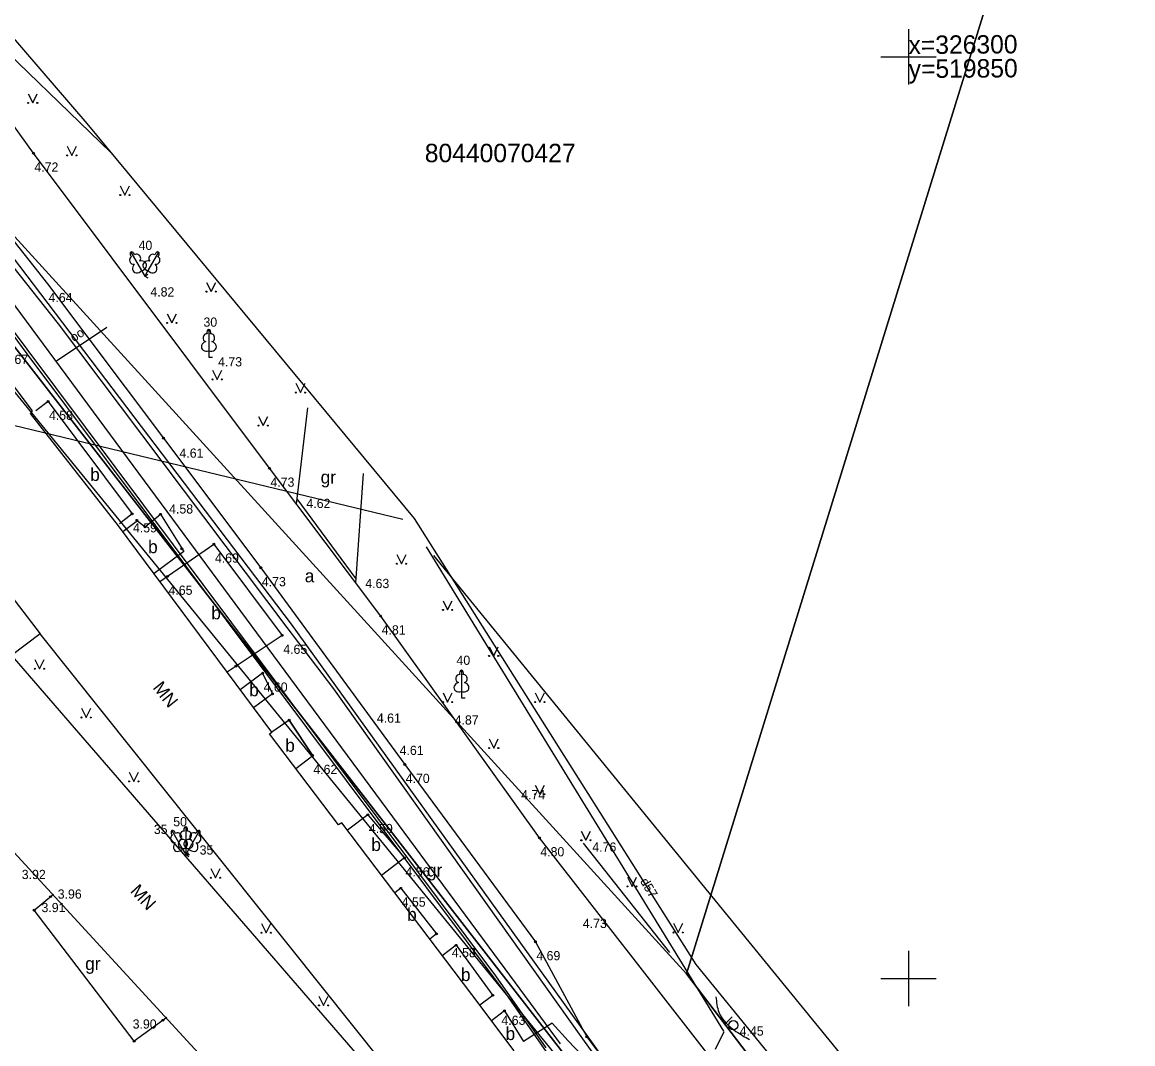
# Model space of a CAD drawing. Extents: x 519536 to 519949, y 326041 to 326519.
# Drawn here: x 519801.9 to 519862.2, y 326246.5 to 326301.9 of the extents above; entities that cross this region are included whole.
import ezdxf

# ---------------------------------------------------------------- set-up
doc = ezdxf.new("R2010")
doc.units = 0
for name, color, linetype in [('APGR_SARK_####_####_#', 7, 'Continuous'), ('BUVE_EKAS_####_####_#', 7, 'Continuous'), ('BUVE_EKAS_BPAL_####_#', 7, 'Continuous'), ('BUVE_EKAS_RAKS_TKST_#', 7, 'Continuous'), ('BUVE_ELEM_####_####_#', 7, 'Continuous'), ('CELI_CMAL_####_####_#', 7, 'Continuous'), ('CELI_CSEG_####_TKST_#', 7, 'Continuous'), ('CELI_TAKA_####_####_#', 7, 'Continuous'), ('ELEK_VADP_ZSPR_####_#', 7, 'Continuous'), ('GAZE_VADP_ASP1_####_#', 7, 'Continuous'), ('GAZE_VADP_ASP1_TKST_#', 7, 'Continuous'), ('GEOD_ELEM_####_####_#', 7, 'Continuous'), ('GEOD_KORD_####_TKST_#', 7, 'Continuous'), ('RAMI_UZMR_####_####_#', 7, 'Continuous'), ('RELJ_AATZ_####_TKST_#', 7, 'Continuous'), ('RELJ_ELEM_####_####_#', 7, 'Continuous'), ('RELJ_HORZ_PAMT_####_#', 7, 'Continuous'), ('ROBZ_IERR_####_####_#', 7, 'Continuous'), ('ROBZ_PROJ_####_####_#', 7, 'Continuous'), ('ROBZ_UZMR_####_####_#', 7, 'Continuous'), ('ROBZ_UZMR_####_TKST_#', 7, 'Continuous'), ('SAKK_IZVK_####_TKST_#', 7, 'Continuous'), ('SAKK_KKAN_####_####_#', 7, 'Continuous'), ('SAKT_VADV_PKAB_####_#', 7, 'Continuous'), ('TERT_DIAM_####_TKST_#', 7, 'Continuous'), ('TERT_ELEM_####_####_#', 7, 'Continuous'), ('TERT_KRND_####_####_#', 7, 'Continuous')]:
    doc.layers.add(name, color=color, linetype=linetype)

msp = doc.modelspace()

# ---------------------------------------------------------------- linework, layer by layer
at = {"layer": 'APGR_SARK_####_####_#'}
for p, q in [((519771.502, 326318.577), (519839.505, 326235.263)), ((519824.229, 326272.956), (519848.672, 326243.009))]:
    msp.add_line(p, q, dxfattribs=at)
at = {"layer": 'BUVE_EKAS_####_####_#'}
for points in [[(519826.305, 326249.13), (519819.255, 326258.455), (519819.074, 326258.332), (519815.338, 326263.273), (519815.461, 326263.364), (519807.157, 326274.561), (519802.379, 326280.656), (519802.486, 326280.797), (519797.912, 326286.858)], [(519801.084, 326271.092), (519802.904, 326268.709)], [(519815.97, 326241.067), (519794.322, 326264.64), (519799.853, 326269.244)], [(519799.853, 326269.244), (519820.912, 326244.923)], [(519821.513, 326245.392), (519802.904, 326268.709)], [(519828.616, 326246.073), (519826.305, 326249.13)]]:
    msp.add_lwpolyline(points, dxfattribs=at)
at = {"layer": 'BUVE_EKAS_BPAL_####_#'}
msp.add_lwpolyline([(519802.904, 326268.709), (519801.347, 326267.519)], dxfattribs=at)
at = {"layer": 'BUVE_ELEM_####_####_#'}
msp.add_circle((519840.493, 326247.47), 0.25, dxfattribs=at)
at = {"layer": 'CELI_CMAL_####_####_#'}
for p, q in [((519803.331, 326281.307), (519802.665, 326280.804)), ((519816.809, 326275.728), (519817.415, 326280.965)), ((519820.019, 326271.461), (519820.445, 326277.403)), ((519807.885, 326275.204), (519807.208, 326274.673)), ((519808.189, 326274.831), (519807.394, 326274.241)), ((519810.687, 326273.16), (519809.08, 326271.968)), ((519814.97, 326266.565), (519813.755, 326265.664)), ((519815.496, 326265.441), (519814.48, 326264.687)), ((519817.687, 326262.08), (519816.766, 326261.384)), ((519820.679, 326258.89), (519819.564, 326258.047)), ((519822.667, 326256.542), (519821.416, 326255.596)), ((519802.583, 326253.712), (519803.625, 326254.58)), ((519822.457, 326254.899), (519822.13, 326254.652)), ((519808, 326246.596), (519802.583, 326253.712)), ((519824.402, 326252.422), (519824.029, 326252.14)), ((519825.464, 326251.806), (519824.712, 326251.237)), ((519827.448, 326249.09), (519826.74, 326248.555)), ((519828.079, 326248.249), (519827.374, 326247.716)), ((519809.77, 326247.892), (519808, 326246.596)), ((519830.678, 326247.588), (519829.123, 326246.591)), ((519830.678, 326247.588), (519831.546, 326246.618)), ((519831.546, 326246.618), (519832.626, 326245.477))]:
    msp.add_line(p, q, dxfattribs=at)
for points in [[(519839.189, 326245.804), (519829.977, 326257.629), (519821.37, 326269.665), (519815.34, 326277.68), (519802.539, 326294.771), (519798.724, 326300.05), (519793.164, 326307.804), (519787.022, 326315.974)], [(519797.68, 326294.786), (519803.307, 326287.694), (519809.593, 326279.318), (519814.875, 326272.28), (519822.676, 326261.61), (519829.759, 326251.994), (519832.548, 326246.837), (519835.264, 326243.212)], [(519803.331, 326281.307), (519807.885, 326275.204)], [(519808.189, 326274.831), (519808.589, 326274.501), (519809.428, 326275.187), (519810.687, 326273.16)], [(519809.402, 326271.535), (519812.33, 326273.562), (519816.035, 326268.616), (519813.039, 326266.63)], [(519814.97, 326266.565), (519815.496, 326265.441)], [(519817.687, 326262.08), (519816.406, 326264.014), (519815.461, 326263.364)], [(519816.406, 326264.014), (519817.687, 326262.08)], [(519820.679, 326258.89), (519822.667, 326256.542)], [(519822.457, 326254.899), (519824.402, 326252.422)], [(519825.464, 326251.806), (519827.448, 326249.09)], [(519828.079, 326248.249), (519829.123, 326246.591)]]:
    msp.add_lwpolyline(points, dxfattribs=at)
at = {"layer": 'CELI_TAKA_####_####_#'}
msp.add_lwpolyline([(519820.035, 326271.683), (519816.843, 326276.026)], dxfattribs=at)
at = {"layer": 'ELEK_VADP_ZSPR_####_#'}
msp.add_line((519827.61, 326250.148), (519799.349, 326287.942), dxfattribs=at)
for points in [[(519830.369, 326246.03), (519828.17, 326249.181), (519802.207, 326283.896), (519795.993, 326292.283), (519770.741, 326312.416), (519767.549, 326319.699), (519768.203, 326324.348), (519772.317, 326338.857)], [(519832.235, 326246.864), (519818.826, 326265.725), (519816.295, 326269.053), (519803.894, 326285.515), (519801.087, 326289.082)], [(519832.53, 326246.969), (519816.537, 326269.231), (519801.397, 326289.168)], [(519830.345, 326246.245), (519827.61, 326250.148)], [(519836.543, 326237.909), (519834.17, 326244.171), (519832.235, 326246.864)], [(519836.785, 326238.116), (519834.436, 326244.315), (519832.53, 326246.969)]]:
    msp.add_lwpolyline(points, dxfattribs=at)
at = {"layer": 'GAZE_VADP_ASP1_####_#'}
for points in [[(519799.445, 326301.842), (519806.723, 326294.826)], [(519823.837, 326273.416), (519839.954, 326247.14)], [(519839.519, 326246.171), (519840, 326247.131)]]:
    msp.add_lwpolyline(points, dxfattribs=at)
at = {"layer": 'GEOD_ELEM_####_####_#'}
for p, q in [((519850, 326301.5), (519850, 326300)), ((519848.5, 326300), (519850, 326300)), ((519850, 326300), (519850, 326298.5)), ((519850, 326300), (519851.5, 326300)), ((519850, 326251.5), (519850, 326250)), ((519848.5, 326250), (519850, 326250)), ((519850, 326250), (519850, 326248.5)), ((519850, 326250), (519851.5, 326250))]:
    msp.add_line(p, q, dxfattribs=at)
at = {"layer": 'RAMI_UZMR_####_####_#'}
msp.add_lwpolyline([(519677.714, 326342.785), (519698.5, 326350), (519731.501, 326357.892), (519737.588, 326345.92), (519745.762, 326337.624), (519750.101, 326341.721), (519757.06, 326345.369), (519768.285, 326348.755), (519787.076, 326359.753), (519805.421, 326337.748), (519789.141, 326322.825), (519795, 326316.434), (519793.447, 326310.334), (519805.429, 326296.386), (519823.19, 326274.962), (519838.453, 326250.764), (519857.773, 326227.07), (519873.021, 326209.453), (519881.37, 326184.273)], dxfattribs=at)
at = {"layer": 'RELJ_ELEM_####_####_#'}
for centre in [(519802.539, 326294.771), (519803.331, 326281.307), (519809.593, 326279.318), (519815.34, 326277.68), (519807.885, 326275.204), (519809.428, 326275.187), (519808.154, 326274.86), (519808.589, 326274.501), (519810.59, 326273.317), (519812.33, 326273.562), (519814.875, 326272.28), (519809.813, 326271.819), (519821.37, 326269.665), (519816.035, 326268.616), (519813.52, 326266.949), (519814.97, 326266.565), (519815.496, 326265.441), (519816.406, 326264.014), (519817.668, 326262.1), (519822.676, 326261.61), (519820.679, 326258.89), (519829.977, 326257.629), (519822.667, 326256.542), (519822.457, 326254.899), (519803.462, 326254.444), (519802.583, 326253.712), (519824.402, 326252.422), (519825.464, 326251.806), (519829.759, 326251.994), (519827.448, 326249.09), (519828.079, 326248.249), (519809.56, 326247.738), (519832.548, 326246.837), (519808, 326246.596)]:
    msp.add_circle(centre, 0.05, dxfattribs=at)
at = {"layer": 'RELJ_HORZ_PAMT_####_#'}
msp.add_line((519840.074, 326247.561), (519840.427, 326247.916), dxfattribs=at)
msp.add_spline([(519839.55, 326249.01), (519839.715, 326248.172), (519840.639, 326247.136), (519841.38, 326246.69)], degree=3, dxfattribs=at)
at = {"layer": 'ROBZ_IERR_####_####_#'}
for p, q in [((519837.956, 326250.254), (519857.532, 326313.584)), ((519866.128, 326213.288), (519837.956, 326250.254))]:
    msp.add_line(p, q, dxfattribs=at)
at = {"layer": 'ROBZ_PROJ_####_####_#'}
for p, q in [((519795.524, 326296.822), (519837.956, 326250.254)), ((519841.088, 326233.318), (519793.426, 326294.677)), ((519837.956, 326250.254), (519866.128, 326213.288))]:
    msp.add_line(p, q, dxfattribs=at)
at = {"layer": 'ROBZ_UZMR_####_####_#'}
for p, q in [((519857.532, 326313.584), (519837.956, 326250.254)), ((519837.956, 326250.254), (519795.524, 326296.822)), ((519793.426, 326294.677), (519841.088, 326233.318))]:
    msp.add_line(p, q, dxfattribs=at)
at = {"layer": 'SAKK_IZVK_####_TKST_#'}
msp.add_line((519803.731, 326283.481), (519806.512, 326285.339), dxfattribs=at)
at = {"layer": 'SAKK_KKAN_####_####_#'}
msp.add_line((519800.046, 326288.464), (519828.098, 326250.529), dxfattribs=at)
msp.add_lwpolyline([(519828.098, 326250.529), (519831.106, 326246.462)], dxfattribs=at)
at = {"layer": 'SAKT_VADV_PKAB_####_#'}
msp.add_lwpolyline([(519822.572, 326274.904), (519730.824, 326297.06)], dxfattribs=at)
at = {"layer": 'TERT_ELEM_####_####_#'}
for p, q in [((519802.25, 326298), (519802.5, 326297.5)), ((519802.5, 326297.5), (519802.75, 326298)), ((519804.371, 326295.154), (519804.621, 326294.654)), ((519804.621, 326294.654), (519804.871, 326295.154)), ((519807.25, 326293), (519807.5, 326292.5)), ((519807.5, 326292.5), (519807.75, 326293)), ((519808.401, 326288.411), (519808.574, 326288.11)), ((519808.747, 326288.411), (519808.574, 326288.11)), ((519808.574, 326288.11), (519808.747, 326288.21)), ((519808.574, 326288.11), (519808.747, 326288.01)), ((519811.923, 326287.764), (519812.173, 326287.264)), ((519812.173, 326287.264), (519812.423, 326287.764)), ((519809.797, 326286.068), (519810.047, 326285.568)), ((519810.047, 326285.568), (519810.297, 326286.068)), ((519812.052, 326284.056), (519812.052, 326283.709)), ((519812.052, 326283.709), (519812.252, 326283.709)), ((519812.25, 326283), (519812.5, 326282.5)), ((519812.5, 326282.5), (519812.75, 326283)), ((519816.769, 326282.291), (519817.019, 326281.791)), ((519817.019, 326281.791), (519817.269, 326282.291)), ((519814.75, 326280.5), (519815, 326280)), ((519815, 326280), (519815.25, 326280.5)), ((519822.25, 326273), (519822.5, 326272.5)), ((519822.5, 326272.5), (519822.75, 326273)), ((519824.75, 326270.5), (519825, 326270)), ((519825, 326270), (519825.25, 326270.5)), ((519827.25, 326268), (519827.5, 326267.5)), ((519827.5, 326267.5), (519827.75, 326268)), ((519802.614, 326267.309), (519802.864, 326266.809)), ((519802.864, 326266.809), (519803.114, 326267.309)), ((519824.75, 326265.5), (519825, 326265)), ((519825, 326265), (519825.25, 326265.5)), ((519825.749, 326265.569), (519825.749, 326265.222)), ((519829.75, 326265.5), (519830, 326265)), ((519830, 326265), (519830.25, 326265.5)), ((519825.749, 326265.222), (519825.949, 326265.222)), ((519805.149, 326264.663), (519805.399, 326264.163)), ((519805.399, 326264.163), (519805.649, 326264.663)), ((519827.25, 326263), (519827.5, 326262.5)), ((519827.5, 326262.5), (519827.75, 326263)), ((519807.728, 326261.199), (519807.978, 326260.699)), ((519807.978, 326260.699), (519808.228, 326261.199)), ((519829.75, 326260.5), (519830, 326260)), ((519830, 326260), (519830.25, 326260.5)), ((519832.25, 326258), (519832.5, 326257.5)), ((519832.5, 326257.5), (519832.75, 326258)), ((519810.623, 326257.028), (519810.796, 326256.727)), ((519810.796, 326257.074), (519810.796, 326256.727)), ((519810.969, 326257.028), (519810.796, 326256.727)), ((519810.796, 326256.727), (519810.969, 326256.827)), ((519810.796, 326256.727), (519810.996, 326256.727)), ((519810.796, 326256.727), (519810.969, 326256.627)), ((519812.16, 326255.972), (519812.41, 326255.472)), ((519812.41, 326255.472), (519812.66, 326255.972)), ((519834.75, 326255.5), (519835, 326255)), ((519835, 326255), (519835.25, 326255.5)), ((519814.915, 326252.984), (519815.165, 326252.484)), ((519815.165, 326252.484), (519815.415, 326252.984)), ((519837.25, 326253), (519837.5, 326252.5)), ((519837.5, 326252.5), (519837.75, 326253)), ((519818.025, 326249.044), (519818.275, 326248.544)), ((519818.275, 326248.544), (519818.525, 326249.044))]:
    msp.add_line(p, q, dxfattribs=at)
for points in [[(519807.824, 326289.409), (519808.401, 326288.411)], [(519808.018, 326289.253), (519808.016, 326289.253)], [(519809.324, 326289.409), (519808.747, 326288.411)], [(519809.285, 326289.163), (519809.285, 326289.164)], [(519812.052, 326285.209), (519812.052, 326284.056)], [(519812.142, 326284.977), (519812.141, 326284.978)], [(519825.749, 326266.722), (519825.749, 326265.569)], [(519825.839, 326266.49), (519825.838, 326266.491)], [(519810.796, 326258.227), (519810.796, 326257.074)], [(519810.046, 326258.026), (519810.623, 326257.028)], [(519810.24, 326257.87), (519810.238, 326257.87)], [(519810.886, 326257.995), (519810.885, 326257.996)], [(519811.546, 326258.026), (519810.969, 326257.028)], [(519811.507, 326257.78), (519811.507, 326257.781)]]:
    msp.add_lwpolyline(points, dxfattribs=at)
for centre, radius in [((519802.25, 326297.5), 0.028), ((519802.75, 326297.5), 0.0263), ((519804.37, 326294.653), 0.028), ((519804.87, 326294.653), 0.0263), ((519807.25, 326292.5), 0.028), ((519807.75, 326292.5), 0.0263), ((519811.922, 326287.264), 0.028), ((519812.422, 326287.264), 0.0263), ((519809.796, 326285.567), 0.028), ((519810.296, 326285.567), 0.0263), ((519812.25, 326282.5), 0.028), ((519812.75, 326282.5), 0.0263), ((519816.768, 326281.791), 0.028), ((519817.268, 326281.791), 0.0263), ((519814.75, 326280), 0.028), ((519815.25, 326280), 0.0263), ((519822.25, 326272.5), 0.028), ((519822.75, 326272.5), 0.0263), ((519824.75, 326270), 0.028), ((519825.25, 326270), 0.0263), ((519827.25, 326267.5), 0.028), ((519827.75, 326267.5), 0.0263), ((519802.613, 326266.808), 0.028), ((519803.113, 326266.808), 0.0263), ((519824.75, 326265), 0.028), ((519825.25, 326265), 0.0263), ((519829.75, 326265), 0.028), ((519830.25, 326265), 0.0263), ((519805.149, 326264.163), 0.028), ((519805.649, 326264.163), 0.0263), ((519827.25, 326262.5), 0.028), ((519827.75, 326262.5), 0.0263), ((519807.728, 326260.698), 0.028), ((519808.228, 326260.698), 0.0263), ((519829.75, 326260), 0.028), ((519830.25, 326260), 0.0263), ((519832.25, 326257.5), 0.028), ((519832.75, 326257.5), 0.0263), ((519812.16, 326255.472), 0.028), ((519812.66, 326255.472), 0.0263), ((519834.75, 326255), 0.028), ((519835.25, 326255), 0.0263), ((519814.914, 326252.483), 0.028), ((519815.414, 326252.483), 0.0263), ((519837.25, 326252.5), 0.028), ((519837.75, 326252.5), 0.0263), ((519818.025, 326248.544), 0.028), ((519818.525, 326248.544), 0.0263)]:
    msp.add_circle(centre, radius, dxfattribs=at)
for centre, major_axis, ratio, start_param, end_param in [((519807.935, 326288.96), (0.073, -0.203), 0.861323, 3.141593, 6.283185), ((519807.899, 326289.279), (0.075, -0.13), 0.707107, 3.14537, 5.287485), ((519807.899, 326289.279), (0.075, -0.13), 0.707107, 0.995701, 3.137816), ((519808.158, 326289.088), (0.14, -0.165), 0.861323, 0, 3.141593), ((519808.355, 326288.668), (-0.313, -0.071), 0.814445, 1.531171, 4.712389), ((519808.793, 326288.668), (0.313, -0.071), 0.814445, 1.570796, 4.752015), ((519808.99, 326289.088), (-0.14, -0.165), 0.861323, 3.141593, 6.283185), ((519809.249, 326289.279), (-0.075, -0.13), 0.707107, 3.14537, 5.287485), ((519809.213, 326288.96), (-0.073, -0.203), 0.861323, 0, 3.141593), ((519809.249, 326289.279), (-0.075, -0.13), 0.707107, 0.995701, 3.137816), ((519808.2, 326288.579), (0.218, 0.236), 0.814445, 1.570796, 4.752015), ((519808.948, 326288.579), (-0.218, 0.236), 0.814445, 1.531171, 4.712389), ((519811.924, 326284.764), (-0.039, -0.212), 0.861323, 3.141593, 6.283185), ((519812.052, 326285.059), (0, -0.15), 0.707107, 3.14537, 5.287485), ((519812.052, 326285.059), (0, -0.15), 0.707107, 0.995701, 3.137816), ((519812.18, 326284.764), (0.039, -0.212), 0.861323, 0, 3.141593), ((519811.962, 326284.302), (0.307, 0.095), 0.814445, 1.570796, 4.752015), ((519812.142, 326284.302), (-0.307, 0.095), 0.814445, 1.531171, 4.712389), ((519825.749, 326266.572), (0, -0.15), 0.707107, 3.14537, 5.287485), ((519825.749, 326266.572), (0, -0.15), 0.707107, 0.995701, 3.137816), ((519825.659, 326265.815), (0.307, 0.095), 0.814445, 1.570796, 4.752015), ((519825.621, 326266.277), (-0.039, -0.212), 0.861323, 3.141593, 6.283185), ((519825.839, 326265.815), (-0.307, 0.095), 0.814445, 1.531171, 4.712389), ((519825.877, 326266.277), (0.039, -0.212), 0.861323, 0, 3.141593), ((519810.796, 326258.077), (0, -0.15), 0.707107, 3.14537, 5.287485), ((519810.796, 326258.077), (0, -0.15), 0.707107, 0.995701, 3.137816), ((519810.157, 326257.577), (0.073, -0.203), 0.861323, 3.141593, 6.283185), ((519810.121, 326257.896), (0.075, -0.13), 0.707107, 3.14537, 5.287485), ((519810.121, 326257.896), (0.075, -0.13), 0.707107, 0.995701, 3.137816), ((519810.38, 326257.705), (0.14, -0.165), 0.861323, 0, 3.141593), ((519810.706, 326257.32), (0.307, 0.095), 0.814445, 1.570796, 4.752015), ((519810.668, 326257.782), (-0.039, -0.212), 0.861323, 3.141593, 6.283185), ((519810.577, 326257.285), (-0.313, -0.071), 0.814445, 1.531171, 4.712389), ((519811.015, 326257.285), (0.313, -0.071), 0.814445, 1.570796, 4.752015), ((519810.886, 326257.32), (-0.307, 0.095), 0.814445, 1.531171, 4.712389), ((519810.924, 326257.782), (0.039, -0.212), 0.861323, 0, 3.141593), ((519811.212, 326257.705), (-0.14, -0.165), 0.861323, 3.141593, 6.283185), ((519811.471, 326257.896), (-0.075, -0.13), 0.707107, 3.14537, 5.287485), ((519811.435, 326257.577), (-0.073, -0.203), 0.861323, 0, 3.141593), ((519811.471, 326257.896), (-0.075, -0.13), 0.707107, 0.995701, 3.137816), ((519810.422, 326257.196), (0.218, 0.236), 0.814445, 1.570796, 4.752015), ((519811.17, 326257.196), (-0.218, 0.236), 0.814445, 1.531171, 4.712389)]:
    msp.add_ellipse(centre, major_axis=major_axis, ratio=ratio, start_param=start_param, end_param=end_param, dxfattribs=at)
at = {"layer": 'TERT_KRND_####_####_#'}
for p, q in [((519834.076, 326255.192), (519832.377, 326257.345)), ((519837.053, 326251.419), (519834.076, 326255.192))]:
    msp.add_line(p, q, dxfattribs=at)

# ---------------------------------------------------------------- texts
at = {"layer": 'BUVE_EKAS_RAKS_TKST_#'}
for rotation, p in [(308.59347, (519808.978, 326265.768)), (312.62131, (519807.749, 326254.717))]:
    msp.add_text('MN', height=0.7, rotation=rotation, dxfattribs=at).set_placement(p)
at = {"layer": 'CELI_CSEG_####_TKST_#'}
for s, p in [('b', (519805.618, 326276.996)), ('gr', (519818.114, 326276.852)), ('b', (519808.756, 326273.077)), ('a', (519817.252, 326271.497)), ('b', (519812.185, 326269.489)), ('b', (519814.239, 326265.315)), ('b', (519816.193, 326262.302)), ('b', (519820.863, 326256.92)), ('gr', (519823.88, 326255.53)), ('b', (519822.804, 326253.131)), ('gr', (519805.345, 326250.463)), ('b', (519825.721, 326249.865)), ('b', (519828.143, 326246.665))]:
    msp.add_text(s, height=0.7, dxfattribs=at).set_placement(p)
at = {"layer": 'GAZE_VADP_ASP1_TKST_#'}
msp.add_text('d57', height=0.5, rotation=300.99272, dxfattribs=at).set_placement((519835.417, 326255.276))
at = {"layer": 'GEOD_KORD_####_TKST_#'}
for s, p in [('x=326300', (519849.999, 326300.15)), ('y=519850', (519850.008, 326298.85))]:
    msp.add_text(s, height=1, rotation=0.39927, dxfattribs=at).set_placement(p)
at = {"layer": 'RELJ_AATZ_####_TKST_#'}
for s, p in [('4.72', (519802.589, 326293.771)), ('4.64', (519803.357, 326286.694)), ('4.82', (519808.879, 326287.001)), ('4.67', (519800.952, 326283.344)), ('4.73', (519812.552, 326283.209)), ('4.58', (519803.381, 326280.307)), ('4.61', (519810.458, 326278.255)), ('4.73', (519815.39, 326276.68)), ('4.58', (519809.897, 326275.227)), ('4.62', (519817.343, 326275.526)), ('4.59', (519807.935, 326274.204)), ('4.69', (519812.38, 326272.562)), ('4.73', (519814.925, 326271.28)), ('4.63', (519820.535, 326271.183)), ('4.65', (519809.863, 326270.819)), ('4.81', (519821.42, 326268.665)), ('4.65', (519816.085, 326267.616)), ('4.60', (519815.02, 326265.565)), ('4.61', (519821.163, 326263.88)), ('4.87', (519825.381, 326263.778)), ('4.61', (519822.398, 326262.132)), ('4.62', (519817.718, 326261.1)), ('4.70', (519822.726, 326260.61)), ('4.74', (519828.99, 326259.723)), ('4.59', (519820.729, 326257.89)), ('4.80', (519830.027, 326256.629)), ('4.76', (519832.846, 326256.884)), ('3.92', (519801.905, 326255.398)), ('4.56', (519822.717, 326255.542)), ('3.96', (519803.855, 326254.336)), ('3.91', (519802.976, 326253.604)), ('4.55', (519822.507, 326253.899)), ('4.73', (519832.333, 326252.742)), ('4.58', (519825.225, 326251.157)), ('4.69', (519829.809, 326250.994)), ('4.63', (519827.918, 326247.489)), ('3.90', (519807.919, 326247.285)), ('4.45', (519840.836, 326246.904))]:
    msp.add_text(s, height=0.5, dxfattribs=at).set_placement(p)
at = {"layer": 'ROBZ_UZMR_####_TKST_#'}
msp.add_text('80440070427', height=1, dxfattribs=at).set_placement((519823.761, 326294.285))
at = {"layer": 'SAKK_IZVK_####_TKST_#'}
msp.add_text('oo', height=0.5, rotation=33.73977, dxfattribs=at).set_placement((519804.733, 326284.511))
at = {"layer": 'TERT_DIAM_####_TKST_#'}
for s, p in [('40', (519808.241, 326289.529)), ('30      ', (519811.759, 326285.362)), ('40      ', (519825.48, 326267.018)), ('35', (519809.066, 326257.843)), ('50      ', (519810.121, 326258.258)), ('35', (519811.552, 326256.726))]:
    msp.add_text(s, height=0.5, dxfattribs=at).set_placement(p)

doc.saveas('drawing.dxf')
